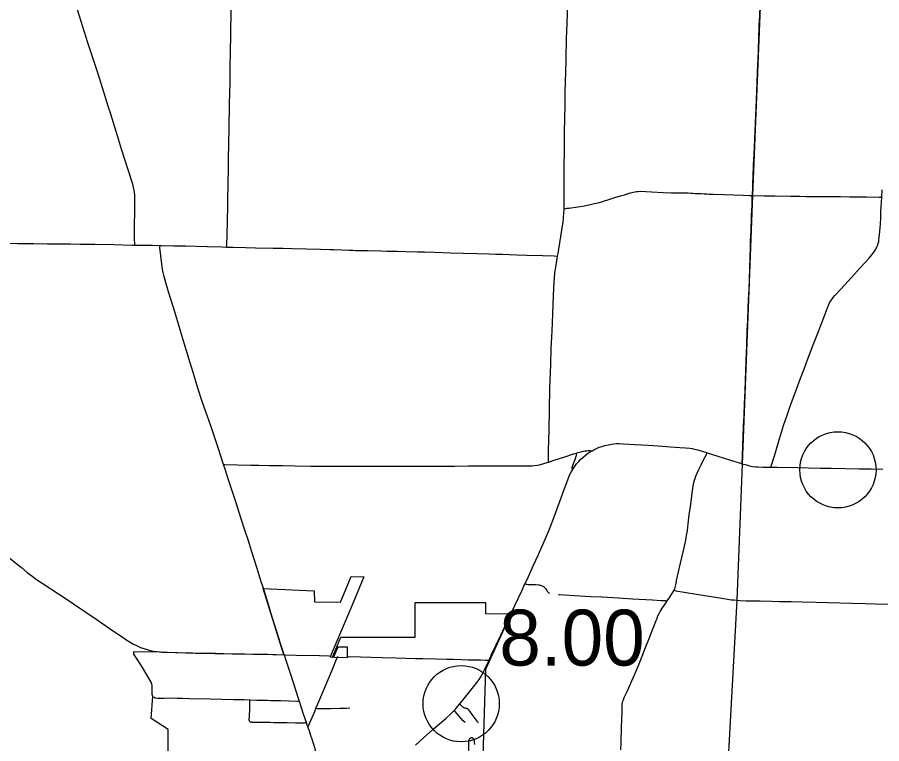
# Model space of a CAD drawing. Extents: x 1815539 to 1947826, y 273303 to 993194.
# Drawn here: x 1852961 to 1869978, y 911339 to 925636 of the extents above; entities that cross this region are included whole.
import ezdxf

# ---------------------------------------------------------------- set-up
doc = ezdxf.new("R2010")
doc.units = 0
for name, color, linetype in [('Default', 7, 'Continuous'), ('GM_X_City_Street', 7, 'Continuous'), ('GM_X_Corporation', 7, 'Continuous'), ('GM_X_County_Road', 7, 'Continuous'), ('GM_X_State_Route', 7, 'Continuous'), ('GM_X_Township', 7, 'Continuous'), ('GM_X_Township_Road', 7, 'Continuous'), ('GM_X_US_Route', 7, 'Continuous')]:
    doc.layers.add(name, color=color, linetype=linetype)

msp = doc.modelspace()

# ---------------------------------------------------------------- linework, layer by layer
at = {"layer": 'Default'}
for centre in [(1869116, 916730), (1861700, 912127)]:
    msp.add_circle(centre, 750, dxfattribs=at)
at = {"layer": 'GM_X_City_Street'}
for points in [[(1858213, 913089), (1858450, 913085), (1858911, 913072), (1859092, 913066), (1859131, 913065)], [(1858841, 912036), (1858879, 912127), (1858974, 912353), (1859184, 912850), (1859234, 912971), (1859260, 913032), (1859273, 913062)], [(1859177, 913063), (1859196, 913063)], [(1859473, 913058), (1859719, 913052), (1860144, 913039), (1860422, 913031), (1860799, 913019), (1860946, 913014), (1861207, 913008), (1861420, 913003), (1861551, 913000), (1861703, 912997), (1861831, 912993), (1862079, 912987), (1862177, 912983), (1862227, 912983), (1862249, 912983)], [(1855645, 912263), (1855655, 912254), (1855671, 912244), (1855687, 912240), (1855720, 912237), (1855751, 912237), (1855851, 912238), (1855983, 912239), (1856115, 912238), (1856213, 912234), (1856345, 912231), (1856756, 912220), (1857216, 912210), (1857430, 912206), (1857543, 912203)], [(1857538, 911775), (1857534, 911782), (1857532, 911789), (1857530, 911798), (1857529, 911805), (1857531, 911885), (1857536, 912017), (1857542, 912180), (1857543, 912203)], [(1857543, 912203), (1857676, 912199), (1857824, 912195), (1857889, 912193), (1857955, 912192), (1858037, 912190), (1858152, 912188), (1858480, 912175), (1858510, 912174)], [(1861671, 912122), (1861679, 912114), (1861699, 912094), (1861719, 912073), (1861731, 912062), (1861744, 912053), (1861759, 912045), (1861775, 912042), (1861791, 912040), (1861806, 912036), (1861821, 912029), (1861833, 912019), (1861864, 911981), (1861912, 911916), (1861968, 911837), (1862009, 911786), (1862030, 911762), (1862042, 911752)], [(1858681, 911663), (1858694, 911691), (1858715, 911735), (1858816, 911976), (1858841, 912036)], [(1858841, 912036), (1858865, 912030), (1858904, 912029), (1858937, 912031), (1858972, 912033), (1859035, 912034), (1859132, 912033), (1859312, 912036), (1859443, 912039), (1859508, 912042)], [(1861777, 911759), (1861742, 911792), (1861697, 911838), (1861654, 911886), (1861580, 911971), (1861560, 911993)], [(1857538, 911775), (1857543, 911771), (1857550, 911768), (1857565, 911767), (1857581, 911766), (1857646, 911766), (1857932, 911760), (1858011, 911758), (1858273, 911755), (1858437, 911750), (1858552, 911749), (1858610, 911751), (1858623, 911754), (1858632, 911759), (1858645, 911766)], [(1861966, 911325), (1861964, 911374), (1861963, 911390), (1861960, 911406), (1861956, 911418), (1861951, 911427), (1861945, 911435), (1861939, 911440), (1861932, 911446), (1861925, 911450), (1861917, 911453), (1861909, 911454), (1861903, 911455), (1861895, 911454), (1861888, 911452), (1861881, 911448), (1861875, 911444), (1861869, 911439), (1861864, 911434), (1861857, 911424), (1861851, 911411), (1861847, 911395), (1861845, 911379), (1861844, 911346), (1861847, 911134)]]:
    msp.add_lwpolyline(points, dxfattribs=at)
at = {"layer": 'GM_X_Corporation'}
msp.add_lwpolyline([(1855933, 910888), (1855933, 911621), (1855597, 911833), (1855631, 912270), (1855619, 912308), (1855615, 912475), (1855611, 912512), (1855597, 912550), (1855405, 912870), (1855257, 913101), (1855254, 913155), (1855764, 913146), (1856077, 913134), (1856467, 913124), (1857604, 913104), (1857896, 913099), (1858210, 913088), (1857802, 914396), (1858808, 914349), (1858812, 914132), (1859323, 914126), (1859536, 914631), (1859785, 914623), (1859564, 914100), (1859120, 913047), (1859167, 913045), (1859333, 913438), (1860795, 913438), (1860795, 914118), (1862176, 914119), (1862176, 913903), (1862676, 913897), (1862176, 912797), (1862124, 911095)], dxfattribs=at)
msp.add_lwpolyline([(1859188, 913044), (1859465, 913038), (1859463, 913238), (1859269, 913236)], close=True, dxfattribs=at)
at = {"layer": 'GM_X_County_Road'}
for points in [[(1867433, 922128), (1867439, 922291), (1867450, 922570), (1867453, 922656), (1867457, 922749), (1867460, 922820), (1867466, 922939), (1867472, 923072), (1867480, 923243), (1867499, 923702), (1867513, 924013), (1867525, 924358), (1867534, 924555), (1867545, 924833), (1867550, 924964), (1867552, 925030), (1867558, 925194), (1867568, 925473), (1867576, 925670), (1867591, 926031), (1867595, 926158)], [(1867232, 916849), (1867232, 916867), (1867238, 917010), (1867259, 917584), (1867268, 917798), (1867277, 918027), (1867288, 918290), (1867294, 918486), (1867309, 918880), (1867321, 919175), (1867331, 919487), (1867340, 919670), (1867342, 919710), (1867350, 919897), (1867359, 920077), (1867368, 920274), (1867374, 920487), (1867381, 920701), (1867388, 920914), (1867393, 921111), (1867398, 921242), (1867406, 921422), (1867418, 921734), (1867425, 921931), (1867431, 922095), (1867433, 922128)], [(1851869, 921200), (1851925, 921198), (1852089, 921195), (1852319, 921193), (1852696, 921189), (1852975, 921187), (1853287, 921182), (1853550, 921180), (1853763, 921178), (1854009, 921176), (1854190, 921173), (1854485, 921168), (1854863, 921162), (1855224, 921154), (1855273, 921153)], [(1855273, 921153), (1855453, 921150), (1855617, 921148), (1855764, 921146)], [(1857023, 916832), (1856919, 917142), (1856769, 917593), (1856674, 917872), (1856604, 918074), (1856517, 918338), (1856448, 918557), (1856339, 918918), (1856184, 919437), (1856121, 919640), (1856035, 919922), (1855938, 920235), (1855877, 920439), (1855850, 920534), (1855831, 920614), (1855820, 920679), (1855806, 920777), (1855767, 921102), (1855766, 921119), (1855764, 921146)], [(1855764, 921146), (1855798, 921145), (1856044, 921141), (1856274, 921136), (1856700, 921124), (1856996, 921116), (1857083, 921114)], [(1857083, 921114), (1857209, 921111), (1857455, 921105), (1857652, 921100), (1857996, 921093), (1858193, 921089), (1858374, 921084), (1858653, 921077), (1858931, 921069), (1859112, 921065), (1859194, 921063), (1859341, 921058), (1859487, 921054), (1859534, 921053), (1859564, 921052), (1859624, 921049), (1859697, 921049), (1859778, 921049), (1859862, 921046), (1860119, 921038), (1860237, 921034), (1860433, 921030), (1860612, 921025), (1860844, 921021), (1860975, 921017), (1861172, 921012), (1861482, 921002), (1861740, 920996), (1862005, 920989), (1862249, 920980), (1862384, 920975), (1862488, 920972)], [(1862488, 920972), (1862514, 920971), (1862645, 920967), (1862795, 920961), (1862991, 920956), (1863299, 920947), (1863532, 920939), (1863596, 920934)], [(1863419, 916883), (1863418, 916971), (1863420, 917102), (1863426, 917322), (1863430, 917511), (1863448, 918330), (1863463, 918805), (1863474, 919116), (1863483, 919345), (1863488, 919462), (1863496, 919623), (1863511, 919983), (1863525, 920310), (1863536, 920506), (1863545, 920604), (1863555, 920686), (1863573, 920799), (1863596, 920934)], [(1863419, 916883), (1863552, 916927), (1863739, 916988), (1863910, 917042), (1863967, 917058)], [(1863897, 916736), (1863889, 916744), (1863886, 916750), (1863883, 916757), (1863883, 916758), (1863882, 916763), (1863883, 916768), (1863884, 916778), (1863911, 916855), (1863947, 916950), (1863964, 916997), (1863968, 917013), (1863969, 917022), (1863970, 917029), (1863969, 917037), (1863969, 917047), (1863967, 917058)], [(1863967, 917058), (1864005, 917069), (1864084, 917090), (1864132, 917100), (1864165, 917104), (1864195, 917108), (1864239, 917108), (1864279, 917106)], [(1857805, 914398), (1857765, 914522), (1857683, 914788), (1857579, 915116), (1857505, 915350), (1857450, 915522), (1857364, 915787), (1857267, 916083), (1857166, 916395), (1857115, 916551), (1857060, 916723), (1857023, 916832)], [(1858213, 913089), (1858136, 913332), (1858045, 913628), (1857982, 913831), (1857899, 914096), (1857845, 914268), (1857805, 914398)], [(1862955, 914483), (1862970, 914481), (1862990, 914476), (1863012, 914475), (1863045, 914474), (1863098, 914473), (1863164, 914471), (1863213, 914468), (1863236, 914466), (1863255, 914462), (1863278, 914454), (1863293, 914448), (1863308, 914441), (1863322, 914432), (1863335, 914422), (1863346, 914410), (1863366, 914384), (1863385, 914357), (1863395, 914344), (1863404, 914330), (1863414, 914318), (1863425, 914308), (1863437, 914299)], [(1865756, 914153), (1865805, 914223), (1865892, 914359)], [(1865892, 914359), (1865923, 914348), (1866091, 914319), (1866334, 914281), (1866869, 914196), (1867015, 914174), (1867067, 914169)], [(1863617, 914277), (1863633, 914276), (1863731, 914270), (1863927, 914257), (1864254, 914239), (1864467, 914227), (1864794, 914208), (1865071, 914190), (1865464, 914168), (1865627, 914160), (1865723, 914156), (1865756, 914153)], [(1867067, 914169), (1867113, 914163), (1867195, 914157), (1867310, 914153), (1867588, 914148), (1867818, 914144), (1867966, 914140), (1868195, 914136), (1868409, 914129), (1868687, 914123), (1868917, 914116), (1869393, 914104), (1869655, 914099), (1869852, 914094), (1870098, 914088)]]:
    msp.add_lwpolyline(points, dxfattribs=at)
at = {"layer": 'GM_X_State_Route'}
for points in [[(1852590, 915151), (1852693, 915077), (1852812, 914989), (1852927, 914898), (1853042, 914804), (1853157, 914711), (1853248, 914641), (1853341, 914574), (1853450, 914500), (1853601, 914402), (1853643, 914374)], [(1853643, 914374), (1853903, 914204), (1854067, 914094), (1854555, 913762), (1854772, 913615), (1854935, 913503), (1854987, 913468)], [(1854987, 913468), (1855098, 913393), (1855181, 913340), (1855252, 913299), (1855296, 913276), (1855360, 913248), (1855390, 913235), (1855452, 913212), (1855515, 913191), (1855578, 913175), (1855643, 913163), (1855708, 913153), (1855781, 913146)], [(1855781, 913146), (1855807, 913144), (1855905, 913139), (1856118, 913134), (1856414, 913128), (1856640, 913123)], [(1856640, 913123), (1856676, 913122), (1856873, 913118), (1857021, 913114), (1857201, 913111), (1857431, 913106), (1857726, 913100), (1857989, 913096), (1858213, 913089)], [(1858213, 913089), (1858258, 912945), (1858330, 912727), (1858397, 912523), (1858437, 912398), (1858503, 912195), (1858510, 912174), (1858590, 911930), (1858645, 911766), (1858647, 911758), (1858664, 911712), (1858667, 911704)], [(1858667, 911704), (1858681, 911663), (1858712, 911572), (1858742, 911478), (1858751, 911452)], [(1858751, 911452), (1858784, 911353), (1858819, 911244), (1858827, 911213), (1858832, 911181), (1858835, 911149), (1858838, 911021)]]:
    msp.add_lwpolyline(points, dxfattribs=at)
at = {"layer": 'GM_X_Township'}
msp.add_lwpolyline([(1862529, 931646), (1862452, 926319), (1863806, 926284), (1864501, 926257), (1864642, 926260), (1866861, 926186), (1867410, 926171), (1867588, 926156), (1867590, 926005), (1867433, 922134), (1867234, 916844), (1867123, 914163), (1866935, 910696)], dxfattribs=at)
at = {"layer": 'GM_X_Township_Road'}
for points in [[(1854779, 923803), (1854583, 924417), (1854498, 924683), (1854352, 925136), (1854253, 925449), (1854119, 925871), (1854036, 926137), (1853947, 926419), (1853919, 926504)], [(1857083, 921114), (1857085, 921152), (1857086, 921169), (1857090, 921333), (1857098, 921645), (1857104, 921907), (1857108, 922120), (1857111, 922268), (1857115, 922432), (1857118, 922596), (1857122, 922842), (1857127, 923154), (1857133, 923450), (1857142, 923926), (1857150, 924352), (1857153, 924549), (1857155, 924713), (1857158, 924910), (1857164, 925337), (1857170, 925747), (1857173, 926010), (1857177, 926305), (1857176, 926440)], [(1863745, 924011), (1863748, 924145), (1863754, 924391), (1863758, 924538), (1863767, 924816), (1863776, 925210), (1863785, 925521), (1863791, 925717), (1863802, 926078), (1863807, 926209), (1863810, 926277)], [(1863727, 921869), (1863729, 921933), (1863730, 922080), (1863728, 922228), (1863728, 922441), (1863728, 922605), (1863729, 922703), (1863731, 922982), (1863736, 923342), (1863741, 923670), (1863744, 923883), (1863744, 923965), (1863745, 923990), (1863745, 924011)], [(1855273, 921153), (1855272, 921191), (1855270, 921256), (1855269, 921486), (1855272, 921863), (1855273, 922077), (1855272, 922144), (1855268, 922189), (1855263, 922234), (1855250, 922288), (1855234, 922352), (1855146, 922634), (1855016, 923040), (1854914, 923369), (1854875, 923494), (1854783, 923792), (1854779, 923803)], [(1863727, 921869), (1863753, 921873), (1863768, 921874), (1863784, 921876), (1863817, 921880), (1863996, 921905), (1864093, 921921), (1864237, 921951), (1864317, 921968), (1864397, 921987), (1864460, 922006), (1864648, 922065), (1864726, 922089), (1864836, 922121), (1864915, 922144), (1865009, 922172), (1865088, 922194), (1865120, 922201), (1865152, 922207), (1865185, 922209), (1865234, 922211), (1865332, 922208), (1865447, 922202), (1865677, 922189), (1865832, 922184), (1865903, 922183), (1865939, 922182), (1865982, 922181), (1866035, 922181), (1866088, 922180), (1866165, 922179), (1866223, 922176), (1866263, 922174), (1866309, 922171), (1866352, 922170), (1866392, 922168), (1866425, 922166), (1866485, 922162), (1866533, 922158), (1866578, 922155), (1866659, 922153), (1866873, 922148), (1867070, 922141), (1867250, 922134), (1867381, 922130), (1867433, 922128)], [(1869978, 922096), (1869984, 922238)], [(1867433, 922128), (1867660, 922122), (1867873, 922120), (1868185, 922118), (1868366, 922114), (1868490, 922112), (1868558, 922111), (1868661, 922111), (1868743, 922112), (1868858, 922110), (1869038, 922108), (1869170, 922107), (1869350, 922104), (1869678, 922101), (1869925, 922097), (1869978, 922096)], [(1867798, 916781), (1867805, 916804), (1867866, 917007), (1867948, 917274), (1868048, 917603), (1868114, 917806), (1868167, 917961), (1868200, 918054), (1868253, 918192), (1868299, 918314), (1868374, 918514), (1868457, 918729), (1868526, 918913), (1868631, 919189), (1868732, 919449), (1868774, 919556), (1868837, 919725), (1868890, 919863), (1868931, 919970), (1868951, 920014), (1868975, 920057), (1868993, 920084), (1869022, 920123), (1869055, 920159), (1869167, 920279), (1869244, 920364), (1869444, 920581), (1869554, 920703), (1869654, 920812), (1869730, 920898), (1869782, 920961), (1869822, 921014), (1869850, 921055), (1869874, 921098), (1869889, 921128), (1869902, 921159), (1869911, 921190), (1869919, 921223), (1869924, 921255), (1869934, 921353), (1869948, 921500), (1869952, 921566), (1869959, 921697), (1869964, 921812), (1869978, 922090), (1869978, 922096)], [(1863596, 920934), (1863609, 920990), (1863622, 921073), (1863682, 921445), (1863705, 921607), (1863714, 921688), (1863723, 921786), (1863727, 921851), (1863727, 921869)], [(1865892, 914359), (1865912, 914415), (1865924, 914463), (1865948, 914575), (1865994, 914783), (1866045, 915007), (1866080, 915167), (1866119, 915343), (1866138, 915439), (1866153, 915536), (1866169, 915667), (1866191, 915846), (1866211, 916008), (1866254, 916317), (1866269, 916414), (1866282, 916478), (1866294, 916526), (1866304, 916557), (1866321, 916603), (1866347, 916663), (1866380, 916738), (1866423, 916826), (1866466, 916915), (1866494, 916969), (1866526, 917031), (1866542, 917064)], [(1857023, 916832), (1857044, 916832), (1857298, 916829), (1857550, 916824), (1857713, 916821), (1857922, 916817), (1858184, 916812), (1858431, 916808), (1858743, 916804), (1858891, 916803), (1859072, 916801), (1859431, 916801), (1859728, 916800), (1860172, 916799), (1860451, 916800), (1860566, 916801), (1860730, 916801), (1860796, 916802), (1861009, 916803), (1861223, 916803), (1861436, 916803), (1861568, 916804), (1861847, 916807), (1862210, 916807), (1862701, 916809), (1863013, 916807), (1863095, 916809), (1863144, 916812), (1863193, 916818), (1863241, 916829), (1863286, 916842), (1863349, 916860), (1863419, 916883)], [(1864843, 911217), (1864848, 911365), (1864858, 911661), (1864867, 911973), (1864870, 912075), (1864872, 912120), (1864877, 912153), (1864883, 912177), (1864893, 912203), (1864911, 912246), (1864965, 912366), (1865088, 912635), (1865134, 912741), (1865189, 912878), (1865261, 913061), (1865326, 913230), (1865398, 913413), (1865525, 913734), (1865555, 913811), (1865574, 913856), (1865596, 913900), (1865620, 913943), (1865665, 914012), (1865711, 914080), (1865756, 914153)]]:
    msp.add_lwpolyline(points, dxfattribs=at)
at = {"layer": 'GM_X_US_Route'}
for points in [[(1862754, 914057), (1862893, 914349), (1862955, 914483), (1863003, 914587), (1863119, 914841), (1863219, 915065), (1863286, 915215), (1863360, 915380), (1863436, 915561), (1863490, 915699), (1863575, 915929), (1863728, 916345), (1863796, 916530), (1863827, 916606), (1863848, 916651), (1863872, 916695), (1863897, 916736), (1863906, 916751), (1863943, 916806), (1863973, 916845), (1864016, 916895), (1864050, 916931), (1864098, 916976), (1864135, 917008), (1864188, 917048), (1864228, 917077), (1864279, 917106), (1864314, 917126), (1864374, 917154), (1864419, 917173), (1864466, 917189), (1864529, 917208), (1864593, 917223), (1864658, 917235), (1864707, 917241), (1864757, 917245), (1864806, 917246), (1864888, 917243), (1865118, 917230), (1865380, 917212), (1865576, 917199), (1865822, 917184), (1866002, 917172), (1866116, 917164), (1866198, 917156), (1866247, 917149), (1866295, 917138), (1866359, 917121), (1866531, 917068), (1866542, 917064), (1866751, 916999), (1867001, 916920), (1867220, 916852), (1867232, 916849), (1867315, 916825), (1867378, 916809), (1867443, 916797), (1867491, 916791), (1867540, 916787), (1867638, 916784), (1867798, 916781), (1867917, 916780), (1868327, 916773), (1868540, 916769), (1868770, 916764), (1868983, 916761), (1869541, 916751), (1869771, 916746), (1870001, 916743)], [(1862679, 913899), (1862684, 913908), (1862754, 914057)], [(1862166, 912804), (1862249, 912983), (1862299, 913092), (1862480, 913477), (1862633, 913803), (1862679, 913899)], [(1860800, 911313), (1860958, 911456), (1861142, 911619), (1861402, 911845), (1861487, 911922), (1861546, 911979), (1861560, 911993), (1861580, 912014), (1861634, 912076), (1861671, 912122), (1861757, 912229), (1861943, 912459), (1862013, 912549), (1862051, 912602), (1862087, 912657), (1862120, 912714), (1862154, 912780), (1862166, 912804)]]:
    msp.add_lwpolyline(points, dxfattribs=at)

# ---------------------------------------------------------------- texts
at = {"layer": 'Default'}
msp.add_text('8.00', height=1100, dxfattribs=at).set_placement((1862450, 912877))

doc.saveas('drawing.dxf')
